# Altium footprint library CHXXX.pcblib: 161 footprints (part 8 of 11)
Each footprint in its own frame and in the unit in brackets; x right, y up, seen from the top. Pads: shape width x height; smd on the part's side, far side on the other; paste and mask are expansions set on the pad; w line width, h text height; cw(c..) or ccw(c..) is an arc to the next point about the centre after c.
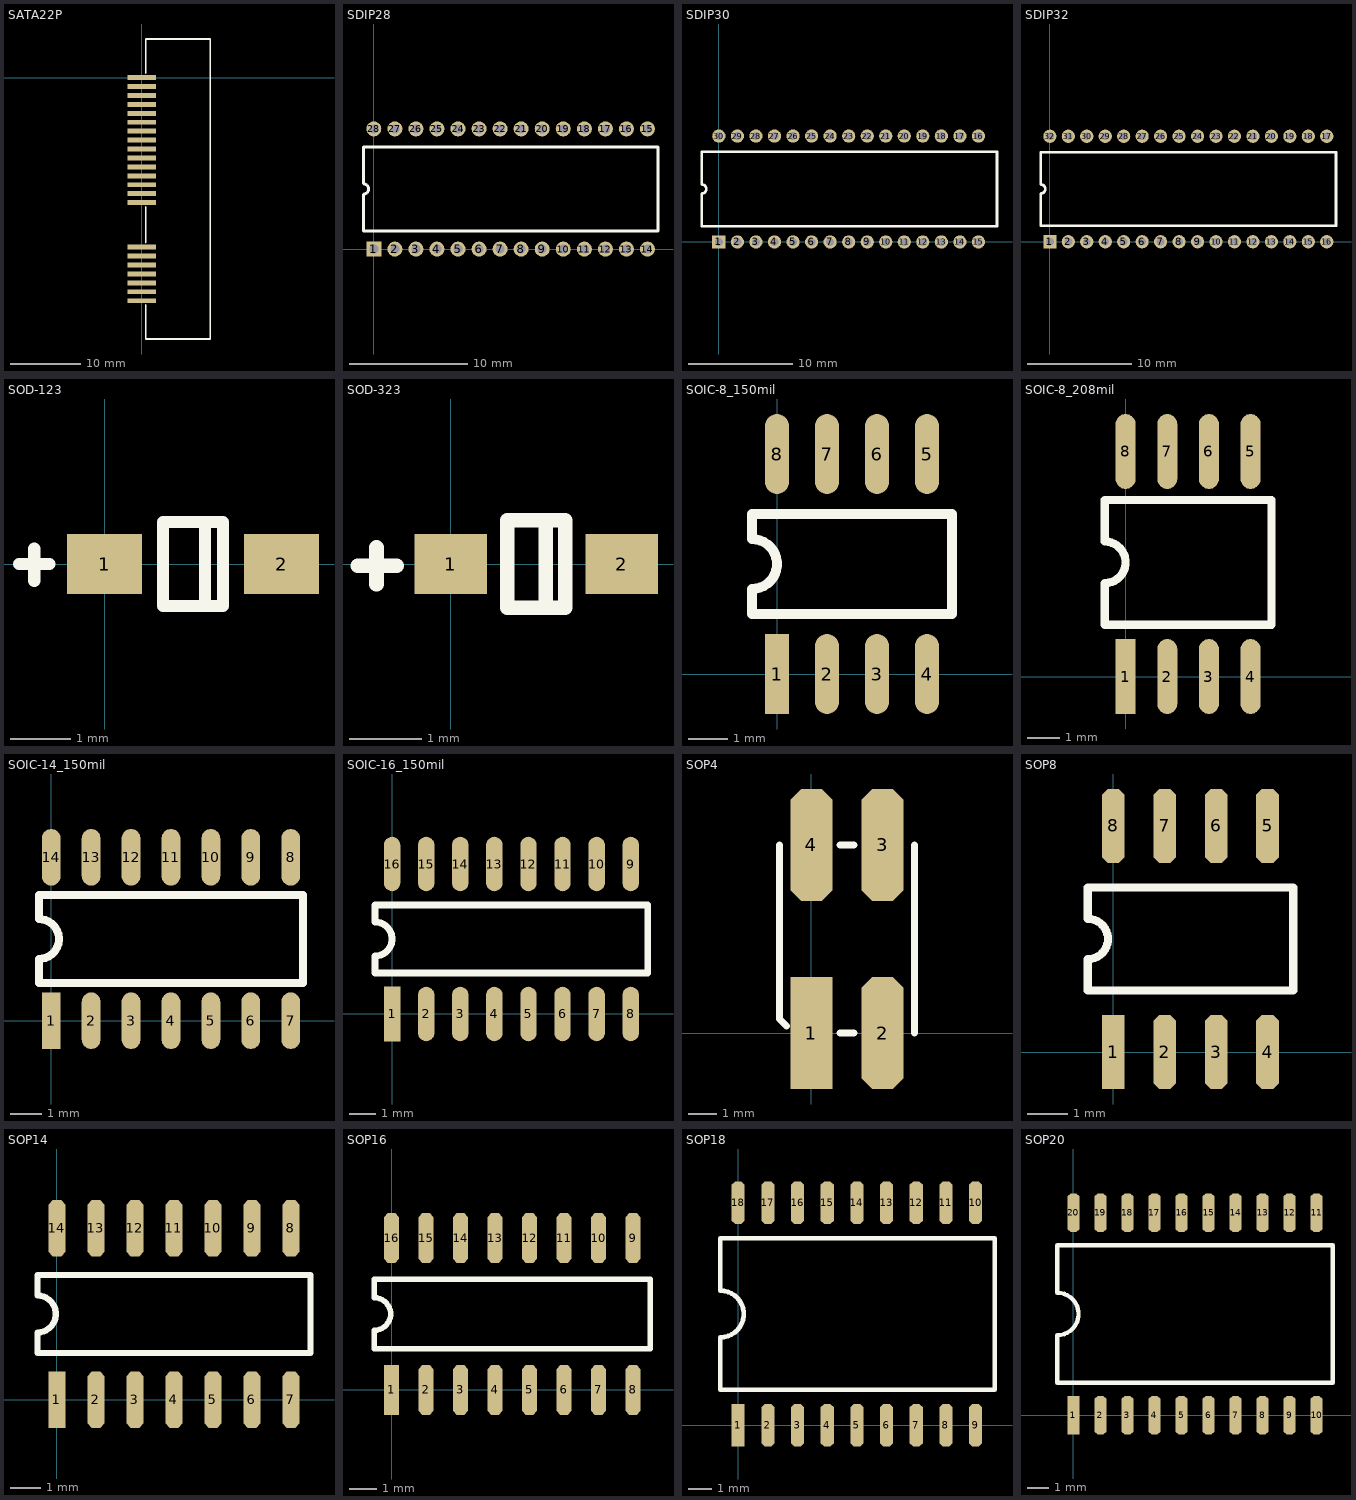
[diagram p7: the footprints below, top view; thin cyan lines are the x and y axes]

## SATA22P [mm]
pads (22):
  rect 4x0.7 smd: 1(0,0) 2(0,-1.27) 3(0,-2.54) 4(0,-3.81) 5(0,-5.08) 6(0,-6.35) 7(0,-7.62) 8(0,-8.89) 9(0,-10.16) 10(0,-11.43) 11(0,-12.7) 12(0,-13.97) 13(0,-15.24) 14(0,-16.51) 15(0,-17.78) 16(0,-24.13) 17(0,-25.4) 18(0,-26.67) 19(0,-27.94) 20(0,-29.21) 21(0,-30.48) 22(0,-31.75)
TopOverlay:
  lines w0.254: 0.551,-32.376 0.551,-37.2 9.751,-37.2 9.751,5.5 0.551,5.5 0.551,0.676 ; 0.551,-23.5 0.551,-18.425

## SDIP28 [mil]
pads (28):
  rect 50x50 hole 30: 1(0,0)
  round 50 hole 30: 2(70,0) 3(140,0) 4(210,0) 5(280,0) 6(350,0) 7(420,0) 8(490,0) 9(560,0) 10(630,0) 11(700,0) 12(770,0) 13(840,0) 14(910,0) 15(910,400) 16(840,400) 17(770,400) 18(700,400) 19(630,400) 20(560,400) 21(490,400) 22(420,400) 23(350,400) 24(280,400) 25(210,400) 26(140,400) 27(70,400) 28(0,400)
TopOverlay:
  lines w10: -35,60 -35,182.5 ccw(c-35,200) -35,217.5 -35,340 945,340 945,60 -35,60

## SDIP30 [mil]
pads (30):
  rect 50x50 hole 30: 1(0,0)
  round 50 hole 30: 2(70,0) 3(140,0) 4(210,0) 5(280,0) 6(350,0) 7(420,0) 8(490,0) 9(560,0) 10(630,0) 11(700,0) 12(770,0) 13(840,0) 14(910,0) 15(980,0) 16(980,400) 17(910,400) 18(840,400) 19(770,400) 20(700,400) 21(630,400) 22(560,400) 23(490,400) 24(420,400) 25(350,400) 26(280,400) 27(210,400) 28(140,400) 29(70,400) 30(0,400)
TopOverlay:
  lines w10: -65,60 1050,60 1050,340 -65,340 -65,217.5 cw(c-65,200) -65,182.5 -65,60

## SDIP32 [mil]
pads (32):
  rect 50x50 hole 30: 1(0,0)
  round 50 hole 30: 2(70,0) 3(140,0) 4(210,0) 5(280,0) 6(350,0) 7(420,0) 8(490,0) 9(560,0) 10(630,0) 11(700,0) 12(770,0) 13(840,0) 14(910,0) 15(980,0) 16(1050,0) 17(1050,400) 18(980,400) 19(910,400) 20(840,400) 21(770,400) 22(700,400) 23(630,400) 24(560,400) 25(490,400) 26(420,400) 27(350,400) 28(280,400) 29(210,400) 30(140,400) 31(70,400) 32(0,400)
TopOverlay:
  lines w10: -35,60 1085,60 1085,340 -35,340 -35,217.5 cw(c-35,200) -35,182.5 -35,60

## SOD-123 [mm]
pads (2):
  rect 1.25x1 smd: 1(0,0) 2(2.95,0)
TopOverlay:
  lines w0.2: 1.675,-0.7 1.675,0.7 ; 0.975,-0.7 1.975,-0.7 1.975,0.7 0.975,0.7 0.975,-0.7
  lines w0.203: -1.43,0 -0.922,0 ; -1.176,-0.279 -1.176,0.254

## SOD-323 [mm]
pads (2):
  rect 1x0.83 smd: 1(0,0) 2(2.36,0)
TopOverlay:
  lines w0.2: 1.31,-0.6 1.31,0.6 ; 0.78,-0.6 1.58,-0.6 1.58,0.6 0.78,0.6 0.78,-0.6
  lines w0.203: -1.278,-0.025 -0.744,-0.025 ; -1.024,-0.279 -1.024,0.229

## SOIC-8_150mil [mil]
pads (8):
  rect 24x80 smd: 1(0,0)
  oval 24x80 smd: 2(50,0) 3(100,0) 4(150,0) 5(150,220) 6(100,220) 7(50,220) 8(0,220)
TopOverlay:
  lines w10: -25,60 175,60 175,160 -25,160 -25,135 cw(c-25,110) -25,85 -25,60

## SOIC-8_208mil [mil]
pads (8):
  rect 24x90 smd: 1(0,0)
  oval 24x90 smd: 2(50,0) 3(100,0) 4(150,0) 5(150,270) 6(100,270) 7(50,270) 8(0,270)
TopOverlay:
  lines w10: -25,62.2 -25,112.01 ccw(c-25,137.01) -25,162.01 -25,211.81 175,211.81 175,62.2 -25,62.2

## SOIC-14_150mil [mm]
pads (14):
  rect 0.6x1.8 smd: 1(0,0)
  oval 0.6x1.8 smd: 2(1.27,0) 3(2.54,0) 4(3.81,0) 5(5.08,0) 6(6.35,0) 7(7.62,0) 8(7.62,5.2) 9(6.35,5.2) 10(5.08,5.2) 11(3.81,5.2) 12(2.54,5.2) 13(1.27,5.2) 14(0,5.2)
TopOverlay:
  lines w0.254: -0.39,1.2 8.01,1.2 8.01,4 -0.39,4 -0.39,3.235 cw(c-0.39,2.6) -0.39,1.965 -0.39,1.2

## SOIC-16_150mil [mil]
pads (16):
  rect 24x80 smd: 1(0,0)
  oval 24x80 smd: 2(50,0) 3(100,0) 4(150,0) 5(200,0) 6(250,0) 7(300,0) 8(350,0) 9(350,220) 10(300,220) 11(250,220) 12(200,220) 13(150,220) 14(100,220) 15(50,220) 16(0,220)
TopOverlay:
  lines w10: -25,60 375,60 375,160 -25,160 -25,135 cw(c-25,110) -25,85 -25,60

## SOP4 [mm]
pads (4):
  rect 1.5x4 smd: 1(0,0)
  oct 1.5x4 smd: 2(2.54,0) 3(2.54,6.726) 4(0,6.726)
TopOverlay:
  lines w0.254: -1.143,6.731 -1.143,0.508 -0.889,0.254 ; 1.016,0 1.524,0 ; 1.016,6.731 1.524,6.731 ; 3.683,0 3.683,6.731

## SOP8 [mil]
pads (8):
  rect 22x72 smd: 1(0,0)
  oct 22x72 smd: 2(50,0) 3(100,0) 4(150,0) 5(150,220) 6(100,220) 7(50,220) 8(0,220)
TopOverlay:
  lines w8: -25,60 175,60 175,160 -25,160 -25,129.69 cw(c-25,110) -25,90.31 -25,60

## SOP14 [mil]
pads (14):
  rect 22x72 smd: 1(0,0)
  oct 22x72 smd: 2(50,0) 3(100,0) 4(150,0) 5(200,0) 6(250,0) 7(300,0) 8(300,220) 9(250,220) 10(200,220) 11(150,220) 12(100,220) 13(50,220) 14(0,220)
TopOverlay:
  lines w8: -25,60 -25,86.38 ccw(c-25,110) -25,133.62 -25,160 325,160 325,60 -25,60

## SOP16 [mil]
pads (16):
  rect 22x72 smd: 1(0,0)
  oct 22x72 smd: 2(50,0) 3(100,0) 4(150,0) 5(200,0) 6(250,0) 7(300,0) 8(350,0) 9(350,220) 10(300,220) 11(250,220) 12(200,220) 13(150,220) 14(100,220) 15(50,220) 16(0,220)
TopOverlay:
  lines w8: -25,60 -25,86.38 ccw(c-25,110) -25,133.62 -25,160 375,160 375,60 -25,60

## SOP18 [mil]
pads (18):
  rect 22x72 smd: 1(0,0)
  oct 22x72 smd: 2(50,0) 3(100,0) 4(150,0) 5(200,0) 6(250,0) 7(300,0) 8(350,0) 9(400,0) 10(400,375) 11(350,375) 12(300,375) 13(250,375) 14(200,375) 15(150,375) 16(100,375) 17(50,375) 18(0,375)
TopOverlay:
  lines w8: -30,60 432,60 432,315 -30,315 -30,226.87 cw(c-30,187.5) -30,148.13 -30,60

## SOP20 [mil]
pads (20):
  rect 22x72 smd: 1(0,0)
  oct 22x72 smd: 2(50,0) 3(100,0) 4(150,0) 5(200,0) 6(250,0) 7(300,0) 8(350,0) 9(400,0) 10(450,0) 11(450,375) 12(400,375) 13(350,375) 14(300,375) 15(250,375) 16(200,375) 17(150,375) 18(100,375) 19(50,375) 20(0,375)
TopOverlay:
  lines w8: -30,147.63 -30,60 480,60 480,315 -30,315 -30,226.87 cw(c-30,187.5) -30,148.13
